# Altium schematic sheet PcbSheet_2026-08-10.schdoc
size 155 x 123 mm
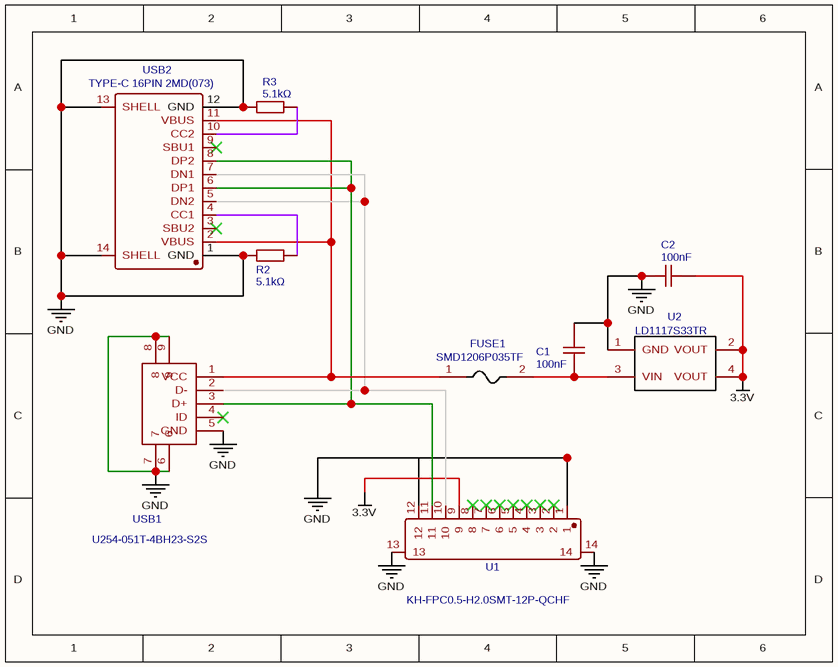
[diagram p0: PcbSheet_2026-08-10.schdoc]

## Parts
C1  100nF  [C1206]
C2  100nF  [C1206]
FUSE1  SMD1206P035TF  [F1206]
R2  5.1kΩ  [R1206]
R3  5.1kΩ  [R1206]
U1  KH-FPC0.5-H2.0SMT-12P-QCHF  [FPC-SMD_12P-P0.50_KH-FPC0.5-H2.0SMT-12P-QCHF]
U2  LD1117S33TR  [SOT-223]
USB1  U254-051T-4BH23-S2S  [MICRO-USB-2.0-5P-5.6X7.15-H3.05-TE]
USB2  TYPE-C 16PIN 2MD(073)  [USB-C-SMD_TYPE-C-6PIN-2MD-073]

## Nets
3.3V: C2.2 U1.9 U2.2(VOUT) U2.4(VOUT)
GND: C1.1 C2.1 R2.1 R3.1 U1.1 U1.12 U1.13 U1.14 U2.1(GND) USB1.5(GND) USB1.6 USB1.7 USB1.8 USB1.9 USB2.1(GND) USB2.12(GND) USB2.13(SHELL) USB2.14(SHELL)
NetC1_2: C1.2 FUSE1.2 U2.3(VIN)
NetFUSE1_1: FUSE1.1 USB1.1(VCC) USB2.2(VBUS) USB2.11(VBUS)
NetR2_2: R2.2 USB2.4(CC1)
NetR3_2: R3.2 USB2.10(CC2)
NetU1_10: U1.10 USB1.2(D-) USB2.5(DN2) USB2.7(DN1)
NetU1_11: U1.11 USB1.3(D+) USB2.6(DP1) USB2.8(DP2)

Not connected (* = marked no-connect by the designer): U1 2* 3* 4* 5* 6* 7* 8*; USB1 4(ID)*; USB2 3(SBU2)* 9(SBU1)*

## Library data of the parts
C1 C2 = 100nF: Manufacturer: YAGEO(国巨); Manufacturer Part: CC1206KRX7R9BB104; nameAlias: Value
FUSE1 = SMD1206P035TF: Manufacturer: RUILON; SMT Type: Extend
R2 R3 = 5.1kΩ: Manufacturer: YAGEO(国巨); Manufacturer Part: RC1206FR-075K1L; nameAlias: Value; Contributor: LCSC
U1 = KH-FPC0.5-H2.0SMT-12P-QCHF: Manufacturer: kinghelm(金航标); Contributor: lcsc
U2 = LD1117S33TR: Manufacturer: STMicroelectronics; Contributor: LCSC
USB1 = U254-051T-4BH23-S2S: Manufacturer: XKB Enterprise; Contributor: LCSC
USB2 = TYPE-C 16PIN 2MD(073): Manufacturer: SHOU HAN(首韩); Contributor: LCSC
